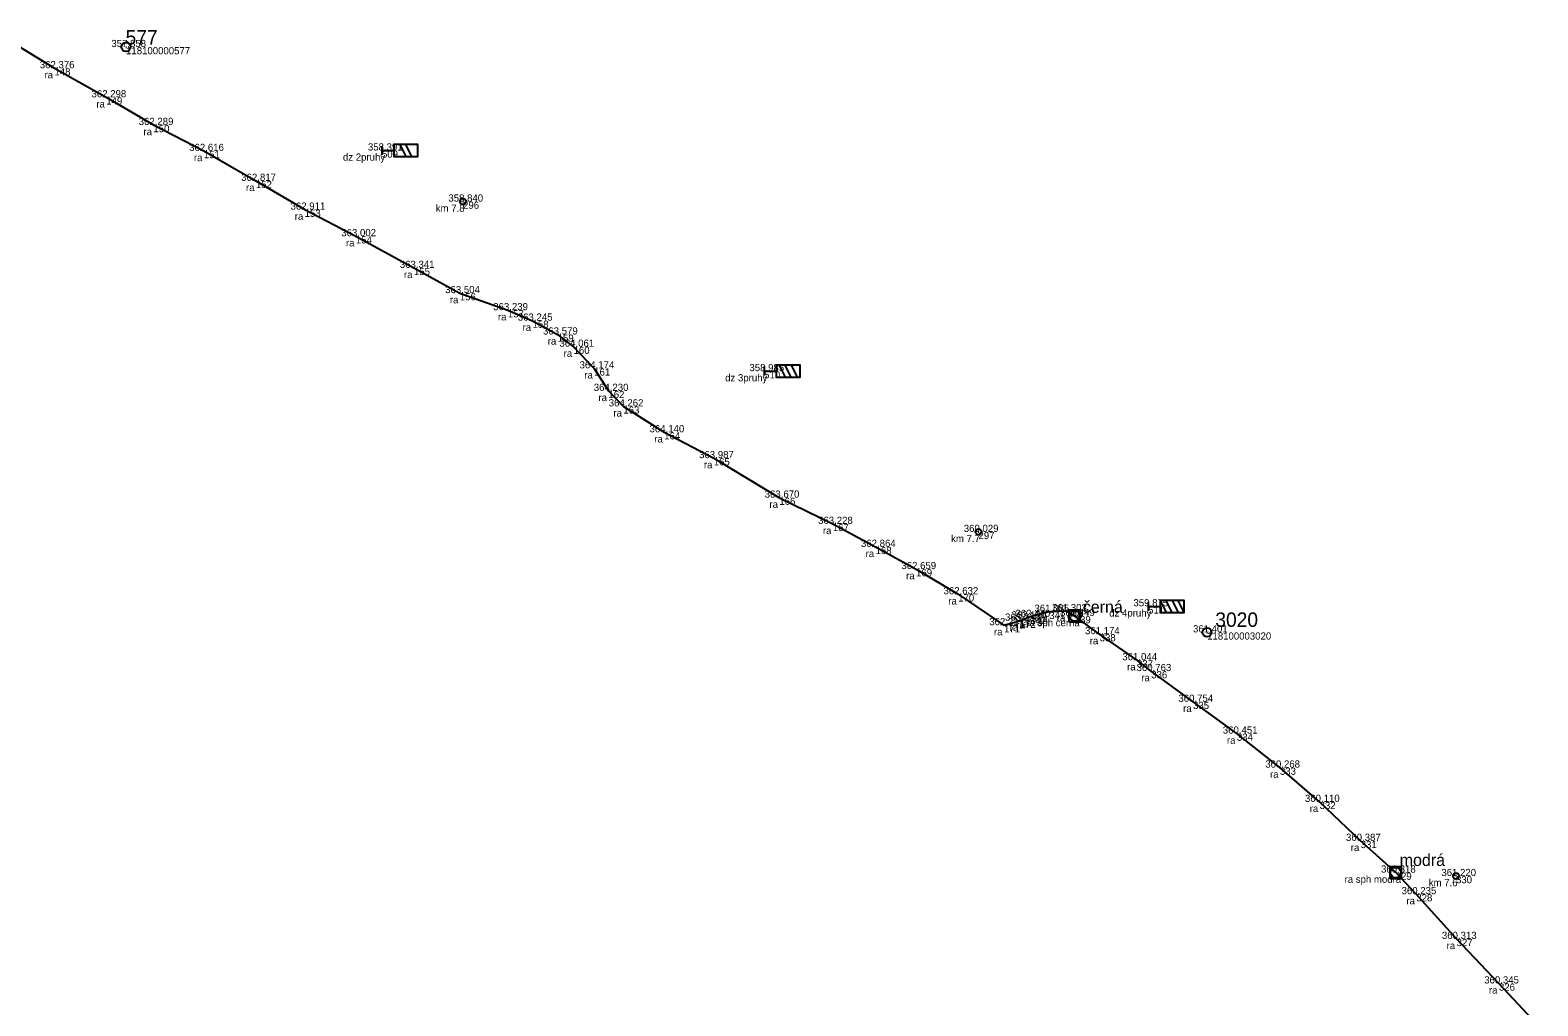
# Model space of a CAD drawing. Extents: x -727171 to -722443, y -945718 to -941834.
# Drawn here: x -725711.1 to -725459.1, y -943691.3 to -943528.4 of the extents above; entities that cross this region are included whole.
import ezdxf

# ---------------------------------------------------------------- set-up
doc = ezdxf.new("R2010")
doc.units = 0
for name, color, linetype in [('Vrstva 28', 7, 'Continuous'), ('Vrstva 33', 7, 'Continuous'), ('Vrstva 60', 7, 'Continuous'), ('Vrstva 61', 7, 'Continuous'), ('Vrstva 62', 7, 'Continuous'), ('Vrstva 63', 7, 'Continuous'), ('Vrstva 7', 7, 'Continuous')]:
    doc.layers.add(name, color=color, linetype=linetype)

msp = doc.modelspace()

# ---------------------------------------------------------------- linework, layer by layer
at = {"layer": 'Vrstva 28'}
for points in [[(-725716.01, -943529.22), (-725707.01, -943534.75), (-725698.35, -943539.61), (-725690.47, -943544.23), (-725682.04, -943548.57), (-725673.34, -943553.56), (-725665.19, -943558.37), (-725656.63, -943562.81), (-725646.93, -943568.1), (-725639.26, -943572.31), (-725631.23, -943575.16), (-725627.11, -943576.91), (-725622.91, -943579.22), (-725620.25, -943581.26), (-725616.8, -943584.88), (-725614.43, -943588.64), (-725611.93, -943591.23), (-725605.1, -943595.55), (-725596.82, -943599.87), (-725585.86, -943606.47), (-725576.93, -943610.85), (-725569.77, -943614.69), (-725563.01, -943618.4), (-725555.97, -943622.61), (-725548.32, -943627.77), (-725545.69, -943627.01), (-725544.61, -943626.64)], [(-725459.1, -943694.57), (-725465.6, -943687.6), (-725472.68, -943680.16), (-725479.41, -943672.69), (-725482.86, -943669.09), (-725488.71, -943663.79), (-725495.57, -943657.27), (-725502.2, -943651.55), (-725509.4, -943645.87), (-725516.72, -943640.56), (-725523.71, -943635.43), (-725526.08, -943633.62), (-725532.33, -943629.27), (-725536.5, -943626.24), (-725537.83, -943625.42), (-725540.76, -943625.54), (-725543.96, -943626.39), (-725544.61, -943626.64)]]:
    msp.add_lwpolyline(points, dxfattribs=at)
at = {"layer": 'Vrstva 33'}
for points in [[(-725537.46, -943627.2), (-725535.54, -943627.2), (-725535.54, -943625.28), (-725537.46, -943625.28)], [(-725483.82, -943670.05), (-725481.9, -943670.05), (-725481.9, -943668.13), (-725483.82, -943668.13)]]:
    msp.add_lwpolyline(points, close=True, dxfattribs=at)
for centre in [(-725536.5, -943626.24), (-725482.86, -943669.09)]:
    msp.add_circle(centre, 0.864, dxfattribs=at)
at = {"layer": 'Vrstva 60'}
for p, q in [((-725695.04, -943531.22), (-725695.04, -943531.22)), ((-725707.01, -943534.75), (-725707.01, -943534.75)), ((-725698.35, -943539.61), (-725698.35, -943539.61)), ((-725690.47, -943544.23), (-725690.47, -943544.23)), ((-725682.04, -943548.57), (-725682.04, -943548.57)), ((-725652.27, -943548.49), (-725652.27, -943548.49)), ((-725673.34, -943553.56), (-725673.34, -943553.56)), ((-725665.19, -943558.37), (-725665.19, -943558.37)), ((-725638.72, -943557.02), (-725638.72, -943557.02)), ((-725656.63, -943562.81), (-725656.63, -943562.81)), ((-725646.93, -943568.1), (-725646.93, -943568.1)), ((-725639.26, -943572.31), (-725639.26, -943572.31)), ((-725631.23, -943575.16), (-725631.23, -943575.16)), ((-725627.11, -943576.91), (-725627.11, -943576.91)), ((-725622.91, -943579.22), (-725622.91, -943579.22)), ((-725620.25, -943581.26), (-725620.25, -943581.26)), ((-725616.8, -943584.88), (-725616.8, -943584.88)), ((-725588.4, -943585.34), (-725588.4, -943585.34)), ((-725614.43, -943588.64), (-725614.43, -943588.64)), ((-725611.93, -943591.23), (-725611.93, -943591.23)), ((-725605.1, -943595.55), (-725605.1, -943595.55)), ((-725596.82, -943599.87), (-725596.82, -943599.87)), ((-725585.86, -943606.47), (-725585.86, -943606.47)), ((-725576.93, -943610.85), (-725576.93, -943610.85)), ((-725552.58, -943612.19), (-725552.58, -943612.19)), ((-725569.77, -943614.69), (-725569.77, -943614.69)), ((-725563.01, -943618.4), (-725563.01, -943618.4)), ((-725555.97, -943622.61), (-725555.97, -943622.61)), ((-725544.61, -943626.64), (-725544.61, -943626.64)), ((-725543.96, -943626.39), (-725543.96, -943626.39)), ((-725540.76, -943625.54), (-725540.76, -943625.54)), ((-725537.83, -943625.42), (-725537.83, -943625.42)), ((-725536.5, -943626.24), (-725536.5, -943626.24)), ((-725524.22, -943624.62), (-725524.22, -943624.62)), ((-725548.32, -943627.77), (-725548.32, -943627.77)), ((-725545.69, -943627.01), (-725545.69, -943627.01)), ((-725532.33, -943629.27), (-725532.33, -943629.27)), ((-725514.37, -943628.97), (-725514.37, -943628.97)), ((-725526.08, -943633.62), (-725526.08, -943633.62)), ((-725523.71, -943635.43), (-725523.71, -943635.43)), ((-725516.72, -943640.56), (-725516.72, -943640.56)), ((-725509.4, -943645.87), (-725509.4, -943645.87)), ((-725502.2, -943651.55), (-725502.2, -943651.55)), ((-725495.57, -943657.27), (-725495.57, -943657.27)), ((-725488.71, -943663.79), (-725488.71, -943663.79)), ((-725482.86, -943669.09), (-725482.86, -943669.09)), ((-725472.77, -943669.66), (-725472.77, -943669.66)), ((-725479.41, -943672.69), (-725479.41, -943672.69)), ((-725472.68, -943680.16), (-725472.68, -943680.16)), ((-725465.6, -943687.6), (-725465.6, -943687.6))]:
    msp.add_line(p, q, dxfattribs=at)
at = {"layer": 'Vrstva 63'}
for p, q in [((-725695.09, -943531.22), (-725694.99, -943531.22)), ((-725514.42, -943628.97), (-725514.32, -943628.97))]:
    msp.add_line(p, q, dxfattribs=at)
for centre in [(-725695.04, -943531.22), (-725514.37, -943628.97)]:
    msp.add_circle(centre, 0.756, dxfattribs=at)
at = {"layer": 'Vrstva 7'}
for p, q in [((-725652.27, -943547.74), (-725652.27, -943549.24)), ((-725649.27, -943547.49), (-725648.27, -943549.49)), ((-725647.27, -943549.49), (-725648.27, -943547.49)), ((-725638.77, -943557.02), (-725638.67, -943557.02)), ((-725588.4, -943584.59), (-725588.4, -943586.09)), ((-725585.9, -943584.34), (-725584.9, -943586.34)), ((-725583.9, -943586.34), (-725584.9, -943584.34)), ((-725583.9, -943584.34), (-725582.9, -943586.34)), ((-725552.64, -943612.19), (-725552.54, -943612.19)), ((-725524.22, -943623.87), (-725524.22, -943625.37)), ((-725522.22, -943623.62), (-725521.22, -943625.62)), ((-725520.22, -943625.62), (-725521.22, -943623.62)), ((-725520.22, -943623.62), (-725519.22, -943625.62)), ((-725518.22, -943625.62), (-725519.22, -943623.62)), ((-725472.82, -943669.66), (-725472.71, -943669.66))]:
    msp.add_line(p, q, dxfattribs=at)
for points in [[(-725652.27, -943548.49), (-725650.27, -943548.49), (-725650.27, -943549.49), (-725646.27, -943549.49), (-725646.27, -943547.49), (-725650.27, -943547.49), (-725650.27, -943548.49)], [(-725588.4, -943585.34), (-725586.4, -943585.34), (-725586.4, -943586.34), (-725582.4, -943586.34), (-725582.4, -943584.34), (-725586.4, -943584.34), (-725586.4, -943585.34)], [(-725524.22, -943624.62), (-725522.22, -943624.62), (-725522.22, -943625.62), (-725518.22, -943625.62), (-725518.22, -943623.62), (-725522.22, -943623.62), (-725522.22, -943624.62)]]:
    msp.add_lwpolyline(points, dxfattribs=at)
for centre in [(-725638.72, -943557.02), (-725552.58, -943612.19), (-725472.77, -943669.66)]:
    msp.add_circle(centre, 0.5, dxfattribs=at)

# ---------------------------------------------------------------- texts
at = {"layer": 'Vrstva 33'}
for s, p in [('černá', (-725535.15, -943625.7)), ('modrá', (-725482.19, -943667.98))]:
    msp.add_text(s, height=2, dxfattribs=at).set_placement(p)
at = {"layer": 'Vrstva 60'}
for s, p in [('118100000577', (-725695.04, -943532.42)), ('148', (-725707.01, -943535.95)), ('149', (-725698.35, -943540.81)), ('150', (-725690.47, -943545.43)), ('151', (-725682.04, -943549.77)), ('509', (-725652.27, -943549.69)), ('152', (-725673.34, -943554.76)), ('153', (-725665.19, -943559.57)), ('296', (-725638.72, -943558.22)), ('154', (-725656.63, -943564.01)), ('155', (-725646.93, -943569.3)), ('156', (-725639.26, -943573.51)), ('157', (-725631.23, -943576.36)), ('158', (-725627.11, -943578.1)), ('159', (-725622.91, -943580.42)), ('160', (-725620.25, -943582.46)), ('161', (-725616.8, -943586.08)), ('510', (-725588.4, -943586.54)), ('162', (-725614.43, -943589.84)), ('163', (-725611.93, -943592.43)), ('164', (-725605.1, -943596.75)), ('165', (-725596.82, -943601.07)), ('166', (-725585.86, -943607.67)), ('167', (-725576.93, -943612.05)), ('297', (-725552.58, -943613.39)), ('168', (-725569.77, -943615.89)), ('169', (-725563.01, -943619.6)), ('170', (-725555.97, -943623.81)), ('173', (-725544.61, -943627.84)), ('342', (-725543.96, -943627.59)), ('341', (-725540.76, -943626.74)), ('340', (-725537.83, -943626.62)), ('339', (-725536.5, -943627.44)), ('511', (-725524.22, -943625.82)), ('171', (-725548.32, -943628.97)), ('172', (-725545.69, -943628.21)), ('338', (-725532.33, -943630.46)), ('118100003020', (-725514.37, -943630.17)), ('337', (-725526.08, -943634.82)), ('336', (-725523.71, -943636.63)), ('335', (-725516.72, -943641.76)), ('334', (-725509.4, -943647.07)), ('333', (-725502.2, -943652.75)), ('332', (-725495.57, -943658.47)), ('331', (-725488.71, -943664.99)), ('329', (-725482.86, -943670.29)), ('330', (-725472.77, -943670.86)), ('328', (-725479.41, -943673.89)), ('327', (-725472.68, -943681.36)), ('326', (-725465.6, -943688.8))]:
    msp.add_text(s, height=1.2, dxfattribs=at).set_placement(p)
at = {"layer": 'Vrstva 61'}
for s, p in [('357.858', (-725697.5, -943531.22)), ('362.376', (-725709.46, -943534.75)), ('362.298', (-725700.81, -943539.61)), ('362.289', (-725692.93, -943544.23)), ('362.616', (-725684.49, -943548.57)), ('358.391', (-725654.62, -943548.49)), ('362.817', (-725675.79, -943553.56)), ('358.840', (-725641.17, -943557.02)), ('362.911', (-725667.55, -943558.37)), ('363.002', (-725659.07, -943562.81)), ('363.341', (-725649.29, -943568.1)), ('363.504', (-725641.71, -943572.31)), ('363.239', (-725633.68, -943575.16)), ('363.245', (-725629.57, -943576.91)), ('363.579', (-725625.36, -943579.22)), ('364.061', (-725622.61, -943581.26)), ('364.174', (-725619.25, -943584.88)), ('358.985', (-725590.86, -943585.34)), ('364.230', (-725616.88, -943588.64)), ('364.262', (-725614.38, -943591.23)), ('364.140', (-725607.55, -943595.55)), ('363.987', (-725599.27, -943599.87)), ('363.670', (-725588.31, -943606.47)), ('363.228', (-725579.39, -943610.85)), ('360.029', (-725555.04, -943612.19)), ('362.864', (-725572.22, -943614.69)), ('362.659', (-725565.46, -943618.4)), ('362.632', (-725558.42, -943622.61)), ('361.303', (-725540.28, -943625.42)), ('359.875', (-725526.68, -943624.62)), ('362.217', (-725550.78, -943627.77)), ('363.220', (-725548.14, -943627.01)), ('363.130', (-725547.06, -943626.64)), ('362.440', (-725546.41, -943626.39)), ('361.085', (-725543.22, -943625.54)), ('361.449', (-725538.95, -943626.24)), ('361.174', (-725534.78, -943629.27)), ('361.401', (-725516.73, -943628.97)), ('361.044', (-725528.54, -943633.62)), ('360.763', (-725526.16, -943635.43)), ('360.754', (-725519.17, -943640.56)), ('360.451', (-725511.75, -943645.87)), ('360.268', (-725504.65, -943651.55)), ('360.110', (-725498.02, -943657.27)), ('360.387', (-725491.16, -943663.79)), ('360.318', (-725485.31, -943669.09)), ('361.220', (-725475.22, -943669.66)), ('360.235', (-725481.87, -943672.69)), ('360.313', (-725475.13, -943680.16)), ('360.345', (-725468.06, -943687.6))]:
    msp.add_text(s, height=1.2, dxfattribs=at).set_placement(p)
at = {"layer": 'Vrstva 62'}
for s, p in [('ra', (-725708.67, -943536.45)), ('ra', (-725700.01, -943541.31)), ('ra', (-725692.14, -943545.93)), ('ra', (-725683.7, -943550.27)), ('dz 2pruhy', (-725658.79, -943550.19)), ('ra', (-725675, -943555.26)), ('km 7.8', (-725643.28, -943558.72)), ('ra', (-725666.85, -943560.07)), ('ra', (-725658.29, -943564.51)), ('ra', (-725648.6, -943569.8)), ('ra', (-725640.93, -943574.01)), ('ra', (-725632.89, -943576.86)), ('ra', (-725628.78, -943578.6)), ('ra', (-725624.57, -943580.92)), ('ra', (-725621.91, -943582.96)), ('ra', (-725618.46, -943586.58)), ('dz 3pruhy', (-725594.92, -943587.04)), ('ra', (-725616.09, -943590.34)), ('ra', (-725613.59, -943592.93)), ('ra', (-725606.76, -943597.25)), ('ra', (-725598.48, -943601.57)), ('ra', (-725587.52, -943608.17)), ('ra', (-725578.59, -943612.55)), ('km 7.7', (-725557.15, -943613.89)), ('ra', (-725571.44, -943616.39)), ('ra', (-725564.67, -943620.1)), ('ra', (-725557.63, -943624.31)), ('ra sph cerna', (-725544.58, -943627.94)), ('ra', (-725542.42, -943627.24)), ('ra', (-725539.49, -943627.12)), ('dz 4pruhy', (-725530.74, -943626.32)), ('ra', (-725549.99, -943629.47)), ('ra', (-725547.35, -943628.71)), ('ra', (-725546.27, -943628.34)), ('ra', (-725545.62, -943628.09)), ('ra', (-725533.99, -943630.96)), ('ra', (-725527.75, -943635.32)), ('ra', (-725525.38, -943637.13)), ('ra', (-725518.38, -943642.26)), ('ra', (-725511.06, -943647.57)), ('ra', (-725503.86, -943653.25)), ('ra', (-725497.23, -943658.97)), ('ra', (-725490.37, -943665.49)), ('ra sph modra', (-725491.4, -943670.79)), ('km 7.6', (-725477.33, -943671.36)), ('ra', (-725481.07, -943674.39)), ('ra', (-725474.34, -943681.86)), ('ra', (-725467.27, -943689.3))]:
    msp.add_text(s, height=1.2, dxfattribs=at).set_placement(p)
at = {"layer": 'Vrstva 63'}
for s, p in [('577', (-725695.12, -943530.79)), ('3020', (-725513, -943628.04))]:
    msp.add_text(s, height=2.4, dxfattribs=at).set_placement(p)

doc.saveas('drawing.dxf')
